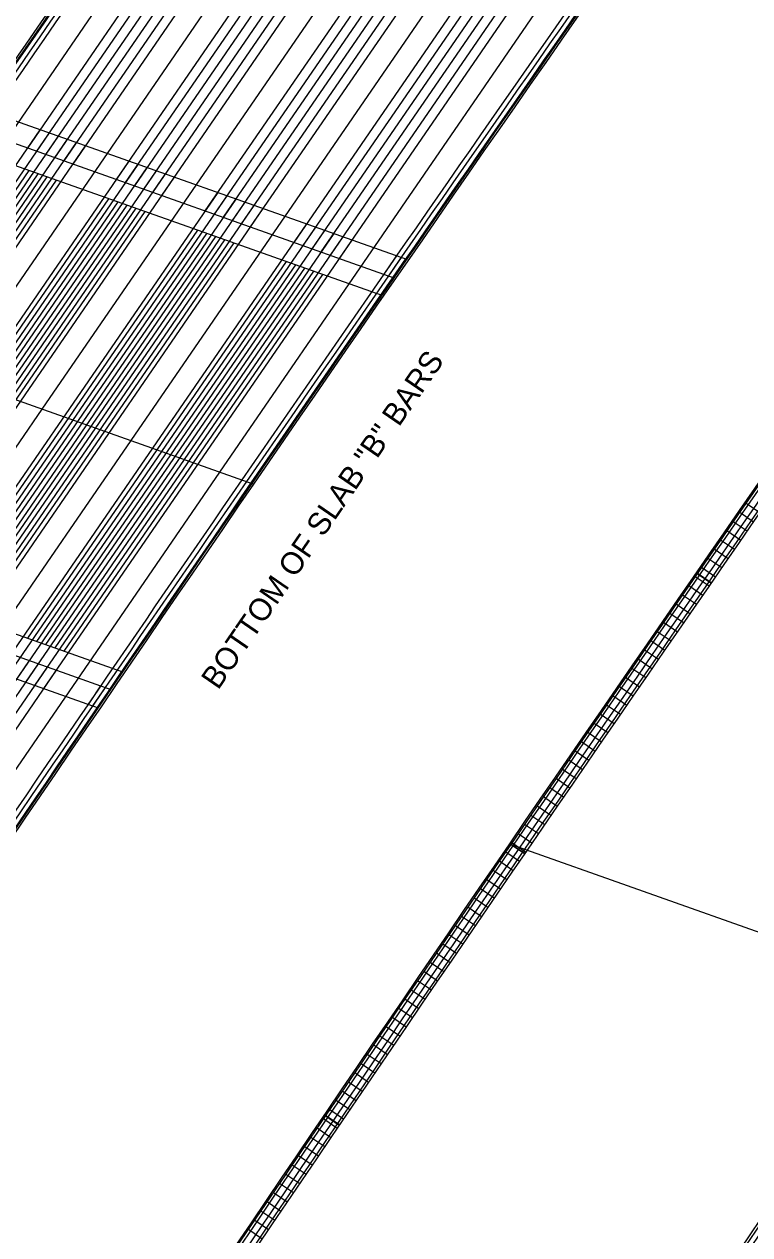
# Model space of a CAD drawing. Extents: x 2378999 to 2381348, y 331302 to 333122.
# Drawn here: x 2379905.9 to 2379971, y 332214.8 to 332323.4 of the extents above; entities that cross this region are included whole.
import ezdxf

# ---------------------------------------------------------------- set-up
doc = ezdxf.new("R2010")
doc.units = 0
for name, color, linetype in [('Arrowhead Terminators', 7, 'Continuous'), ('Dimension Lines', 7, 'Continuous'), ('Mis Work Point CELL', 7, 'Continuous'), ('P_SMU_Centerline_Joint', 7, 'Continuous'), ('P_SMU_Concrete_Barrier_Rail', 7, 'Continuous'), ('P_SMU_Mis_Center_Lines', 7, 'Continuous'), ('P_SMU_Mis_L_Lines', 7, 'Continuous'), ('Scratch_Level_0', 7, 'Continuous'), ('Sup Concrete Slab Lines', 7, 'Continuous')]:
    doc.layers.add(name, color=color, linetype=linetype)

msp = doc.modelspace()

# ---------------------------------------------------------------- linework, layer by layer
at = {"layer": 'Arrowhead Terminators'}
for p, q in [((2379906.23, 332312.27), (2379936.77, 332356.73)), ((2379907.05, 332311.99), (2379937.59, 332356.44)), ((2379907.86, 332311.7), (2379938.4, 332356.15)), ((2379908.67, 332311.41), (2379939.21, 332355.86)), ((2379909.49, 332311.12), (2379940.03, 332355.57)), ((2379910.3, 332310.83), (2379940.84, 332355.29)), ((2379914.2, 332309.45), (2379944.74, 332353.91)), ((2379915.02, 332309.17), (2379945.56, 332353.62)), ((2379915.83, 332308.88), (2379946.37, 332353.33)), ((2379916.64, 332308.59), (2379947.18, 332353.04)), ((2379917.46, 332308.3), (2379948, 332352.75)), ((2379918.27, 332308.01), (2379948.81, 332352.47)), ((2379922.17, 332306.63), (2379952.71, 332351.08)), ((2379922.99, 332306.34), (2379953.53, 332350.8)), ((2379923.8, 332306.06), (2379954.34, 332350.51)), ((2379924.61, 332305.77), (2379955.15, 332350.22)), ((2379925.43, 332305.48), (2379955.97, 332349.93)), ((2379926.24, 332305.19), (2379956.78, 332349.65)), ((2379930.14, 332303.81), (2379960.68, 332348.26)), ((2379930.96, 332303.52), (2379961.5, 332347.98)), ((2379931.77, 332303.24), (2379962.31, 332347.69)), ((2379932.58, 332302.95), (2379963.12, 332347.4)), ((2379933.4, 332302.66), (2379963.94, 332347.11)), ((2379934.21, 332302.37), (2379964.75, 332346.82)), ((2379879.71, 332273.67), (2379907.36, 332313.92)), ((2379880.53, 332273.39), (2379908.18, 332313.63)), ((2379881.34, 332273.1), (2379908.99, 332313.35)), ((2379882.15, 332272.81), (2379909.8, 332313.06)), ((2379882.97, 332272.52), (2379910.62, 332312.77)), ((2379883.78, 332272.23), (2379911.43, 332312.48)), ((2379887.68, 332270.85), (2379915.34, 332311.1)), ((2379888.5, 332270.56), (2379916.15, 332310.81)), ((2379889.31, 332270.28), (2379916.96, 332310.53)), ((2379883.15, 332276.47), (2379906.37, 332310.26)), ((2379883.96, 332276.18), (2379907.18, 332309.97)), ((2379884.78, 332275.89), (2379907.99, 332309.69)), ((2379885.59, 332275.61), (2379908.81, 332309.4)), ((2379890.12, 332269.99), (2379917.78, 332310.24)), ((2379890.94, 332269.7), (2379918.59, 332309.95)), ((2379891.75, 332269.41), (2379919.4, 332309.66)), ((2379895.65, 332268.03), (2379923.31, 332308.28)), ((2379890.31, 332273.94), (2379913.52, 332307.73)), ((2379891.12, 332273.65), (2379914.34, 332307.44)), ((2379891.93, 332273.36), (2379915.15, 332307.15)), ((2379896.47, 332267.74), (2379924.12, 332307.99)), ((2379897.28, 332267.46), (2379924.93, 332307.7)), ((2379898.09, 332267.17), (2379925.75, 332307.42)), ((2379898.91, 332266.88), (2379926.56, 332307.13)), ((2379892.75, 332273.07), (2379915.96, 332306.87)), ((2379893.56, 332272.78), (2379916.78, 332306.58)), ((2379899.72, 332266.59), (2379927.37, 332306.84)), ((2379898.28, 332271.12), (2379921.49, 332304.91)), ((2379903.62, 332265.21), (2379931.28, 332305.46)), ((2379904.44, 332264.92), (2379932.09, 332305.17)), ((2379905.25, 332264.63), (2379932.9, 332304.88)), ((2379899.09, 332270.83), (2379922.31, 332304.62)), ((2379899.9, 332270.54), (2379923.12, 332304.33)), ((2379900.72, 332270.25), (2379923.93, 332304.04)), ((2379906.06, 332264.35), (2379933.72, 332304.6)), ((2379906.88, 332264.06), (2379934.53, 332304.31)), ((2379907.69, 332263.77), (2379935.34, 332304.02)), ((2379901.53, 332269.96), (2379924.75, 332303.76)), ((2379906.25, 332268.29), (2379929.46, 332302.09)), ((2379907.06, 332268.01), (2379930.28, 332301.8)), ((2379907.87, 332267.72), (2379931.09, 332301.51)), ((2379908.69, 332267.43), (2379931.9, 332301.22)), ((2379909.5, 332267.14), (2379932.72, 332300.94)), ((2379875.71, 332221.64), (2379906.38, 332266.28)), ((2379876.53, 332221.36), (2379907.2, 332266)), ((2379877.34, 332221.07), (2379908.01, 332265.71)), ((2379878.15, 332220.78), (2379908.82, 332265.42))]:
    msp.add_line(p, q, dxfattribs=at)
for radius, start, end in [(7099.38, 144.934254, 145.370258), (7098.96, 144.933316, 145.369348), (7098.54, 144.932379, 145.368438), (7061.46, 144.848482, 145.287006), (7061.04, 144.847534, 145.286086), (7060.63, 144.846586, 145.285166), (7061.46, 145.270761, 145.667064), (7061.04, 145.26984, 145.666168), (7060.63, 145.268919, 145.665272), (7061.46, 145.650848, 146.089566), (7061.04, 145.649951, 146.088696), (7060.63, 145.649054, 146.087827)]:
    msp.add_arc((2385742.82, 328279.7), radius, start, end, dxfattribs=at)
at = {"layer": 'Dimension Lines'}
for p, q in [((2379970.7, 332280.42), (2379971.93, 332279.56)), ((2379970.13, 332279.59), (2379971.36, 332278.74)), ((2379968.99, 332277.95), (2379970.23, 332277.1)), ((2379969.56, 332278.77), (2379970.79, 332277.92)), ((2379968.42, 332277.13), (2379969.66, 332276.27)), ((2379967.85, 332276.31), (2379969.09, 332275.45)), ((2379966.71, 332274.66), (2379967.95, 332273.81)), ((2379967.28, 332275.48), (2379968.52, 332274.63)), ((2379966.15, 332273.84), (2379967.38, 332272.99)), ((2379965.58, 332273.02), (2379966.81, 332272.16)), ((2379964.44, 332271.37), (2379965.67, 332270.52)), ((2379965.01, 332272.2), (2379966.24, 332271.34)), ((2379963.87, 332270.55), (2379965.1, 332269.7)), ((2379963.3, 332269.73), (2379964.54, 332268.87)), ((2379962.17, 332268.08), (2379963.4, 332267.23)), ((2379962.73, 332268.9), (2379963.97, 332268.05)), ((2379961.6, 332267.26), (2379962.83, 332266.41)), ((2379961.03, 332266.44), (2379962.26, 332265.58)), ((2379959.89, 332264.79), (2379961.13, 332263.94)), ((2379960.46, 332265.61), (2379961.7, 332264.76)), ((2379959.33, 332263.97), (2379960.56, 332263.11)), ((2379958.76, 332263.14), (2379959.99, 332262.29)), ((2379957.62, 332261.5), (2379958.86, 332260.65)), ((2379958.19, 332262.32), (2379959.43, 332261.47)), ((2379957.06, 332260.67), (2379958.29, 332259.82)), ((2379956.49, 332259.85), (2379957.72, 332259)), ((2379955.35, 332258.2), (2379956.59, 332257.35)), ((2379955.92, 332259.03), (2379957.16, 332258.17)), ((2379954.79, 332257.38), (2379956.02, 332256.53)), ((2379954.22, 332256.55), (2379955.46, 332255.7)), ((2379953.09, 332254.91), (2379954.32, 332254.06)), ((2379953.65, 332255.73), (2379954.89, 332254.88)), ((2379952.52, 332254.08), (2379953.76, 332253.23)), ((2379951.96, 332253.26), (2379953.19, 332252.41)), ((2379951.39, 332252.43), (2379952.63, 332251.58)), ((2379950.26, 332250.78), (2379951.49, 332249.94)), ((2379950.82, 332251.61), (2379952.06, 332250.76)), ((2379949.69, 332249.96), (2379950.93, 332249.11)), ((2379949.13, 332249.13), (2379950.36, 332248.29)), ((2379948, 332247.49), (2379949.23, 332246.64)), ((2379948.56, 332248.31), (2379949.8, 332247.46)), ((2379947.43, 332246.66), (2379948.67, 332245.81)), ((2379946.87, 332245.84), (2379948.1, 332244.99)), ((2379945.74, 332244.19), (2379946.97, 332243.34)), ((2379946.3, 332245.01), (2379947.54, 332244.16)), ((2379945.17, 332243.36), (2379946.41, 332242.51)), ((2379944.61, 332242.53), (2379945.84, 332241.69)), ((2379943.48, 332240.88), (2379944.71, 332240.04)), ((2379944.04, 332241.71), (2379945.28, 332240.86)), ((2379942.91, 332240.06), (2379944.15, 332239.21)), ((2379942.35, 332239.23), (2379943.59, 332238.39)), ((2379941.22, 332237.58), (2379942.46, 332236.74)), ((2379941.78, 332238.41), (2379943.02, 332237.56)), ((2379940.66, 332236.76), (2379941.89, 332235.91)), ((2379940.09, 332235.93), (2379941.33, 332235.08)), ((2379938.96, 332234.28), (2379940.2, 332233.43)), ((2379939.53, 332235.1), (2379940.77, 332234.26)), ((2379938.4, 332233.45), (2379939.64, 332232.61)), ((2379937.84, 332232.62), (2379939.08, 332231.78)), ((2379937.28, 332231.8), (2379938.51, 332230.95)), ((2379936.15, 332230.15), (2379937.39, 332229.3)), ((2379936.71, 332230.97), (2379937.95, 332230.13)), ((2379935.59, 332229.32), (2379936.83, 332228.47)), ((2379935.02, 332228.49), (2379936.26, 332227.65)), ((2379933.9, 332226.84), (2379935.14, 332226)), ((2379934.46, 332227.67), (2379935.7, 332226.82)), ((2379933.34, 332226.01), (2379934.58, 332225.17)), ((2379932.77, 332225.19), (2379934.01, 332224.34)), ((2379931.65, 332223.53), (2379932.89, 332222.69)), ((2379932.21, 332224.36), (2379933.45, 332223.51)), ((2379931.09, 332222.7), (2379932.33, 332221.86)), ((2379930.53, 332221.88), (2379931.77, 332221.03)), ((2379929.4, 332220.22), (2379930.64, 332219.38)), ((2379929.96, 332221.05), (2379931.21, 332220.21)), ((2379928.84, 332219.39), (2379930.08, 332218.55)), ((2379928.28, 332218.57), (2379929.52, 332217.72)), ((2379927.16, 332216.91), (2379928.4, 332216.07)), ((2379927.72, 332217.74), (2379928.96, 332216.9)), ((2379926.6, 332216.08), (2379927.84, 332215.24)), ((2379926.04, 332215.26), (2379927.28, 332214.41))]:
    msp.add_line(p, q, dxfattribs=at)
at = {"layer": 'Mis Work Point CELL'}
for p, q in [((2379888.21, 332295.69), (2379926.51, 332282.13)), ((2379949.47, 332249.85), (2379987.77, 332236.29))]:
    msp.add_line(p, q, dxfattribs=at)
at = {"layer": 'P_SMU_Centerline_Joint'}
for p, q in [((2379967.56, 332273.24), (2379966.32, 332274.1)), ((2379950.82, 332248.96), (2379949.59, 332249.8)), ((2379934.19, 332224.6), (2379932.95, 332225.44))]:
    msp.add_line(p, q, dxfattribs=at)
at = {"layer": 'P_SMU_Concrete_Barrier_Rail'}
for centre, radius, start, end in [((2385921.52, 328197.49), 7099.63, 143.718956, 147.299684), ((2385678.87, 328323.64), 7060.38, 144.837589, 146.095684), ((2385742.82, 328279.7), 7099.63, 144.926438, 146.177079), ((2385742.82, 328279.7), 7060.38, 144.837589, 146.095684), ((2385804.08, 328233.86), 7099.63, 144.926438, 146.177079), ((2385804.08, 328233.86), 7060.38, 144.837589, 146.095684)]:
    msp.add_arc(centre, radius, start, end, dxfattribs=at)
at = {"layer": 'P_SMU_Mis_Center_Lines'}
for p, q in [((2379967.54, 332273.23), (2379966.31, 332274.08)), ((2379967.57, 332273.26), (2379966.33, 332274.11)), ((2379950.81, 332248.94), (2379949.57, 332249.79)), ((2379950.83, 332248.97), (2379949.6, 332249.82)), ((2379934.18, 332224.58), (2379932.94, 332225.43)), ((2379934.2, 332224.62), (2379932.96, 332225.46))]:
    msp.add_line(p, q, dxfattribs=at)
for radius, start, end in [(7099.5, 144.933138, 146.16988), (7098, 144.929763, 146.166785), (7098.69, 144.947312, 146.151932), (7062, 144.84831, 146.092092), (7060.5, 144.844897, 146.088963), (7061.31, 144.863116, 146.07456)]:
    msp.add_arc((2385804.08, 328233.86), radius, start, end, dxfattribs=at)
at = {"layer": 'P_SMU_Mis_L_Lines'}
for p, q in [((2379891.59, 332294.49), (2379935.41, 332358.27)), ((2379899.56, 332291.67), (2379943.38, 332355.45)), ((2379907.53, 332288.85), (2379951.35, 332352.63)), ((2379915.5, 332286.03), (2379959.32, 332349.81)), ((2379923.47, 332283.2), (2379967.29, 332346.99)), ((2379863.58, 332224.88), (2379907.53, 332288.85)), ((2379871.55, 332222.06), (2379915.5, 332286.03)), ((2379879.52, 332219.24), (2379923.47, 332283.2))]:
    msp.add_line(p, q, dxfattribs=at)
at = {"layer": 'Scratch_Level_0'}
for p, q in [((2379902.22, 332315.74), (2379940.23, 332302.29)), ((2379901.09, 332314.1), (2379939.1, 332300.64)), ((2379899.99, 332312.52), (2379938, 332299.07)), ((2379876.8, 332278.72), (2379914.75, 332265.28)), ((2379875.73, 332277.13), (2379913.68, 332263.7)), ((2379874.6, 332275.48), (2379912.55, 332262.05))]:
    msp.add_line(p, q, dxfattribs=at)
for centre, radius, start, end in [((2385678.87, 328323.64), 7060.54, 144.846397, 146.087653), ((2385742.82, 328279.7), 7099.46, 144.934441, 146.168406), ((2385742.82, 328279.7), 7060.54, 144.846397, 146.087653), ((2385804.08, 328233.86), 7099.27, 144.934019, 146.168019), ((2385804.08, 328233.86), 7098.23, 144.931676, 146.165869), ((2385804.08, 328233.86), 7061.77, 144.849193, 146.090218), ((2385804.08, 328233.86), 7060.73, 144.846823, 146.088044)]:
    msp.add_arc(centre, radius, start, end, dxfattribs=at)

# ---------------------------------------------------------------- texts
at = {"layer": 'Sup Concrete Slab Lines'}
msp.add_text('BOTTOM OF SLAB "B" BARS', height=2, rotation=55.5093, dxfattribs=at).set_placement((2379923.32, 332263.58))

doc.saveas('drawing.dxf')
